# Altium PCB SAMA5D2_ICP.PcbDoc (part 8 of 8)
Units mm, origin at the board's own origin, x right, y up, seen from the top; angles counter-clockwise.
Board outline 150 x 100 mm, 6 copper layers (L1 - TOP, L2 - GND, L3 - SIG, L4 - SIG, L5 - VCC, L6 - BOT), stack 1.512 mm thick; 708 components, 597 nets, 2710 pads, 1437 vias.
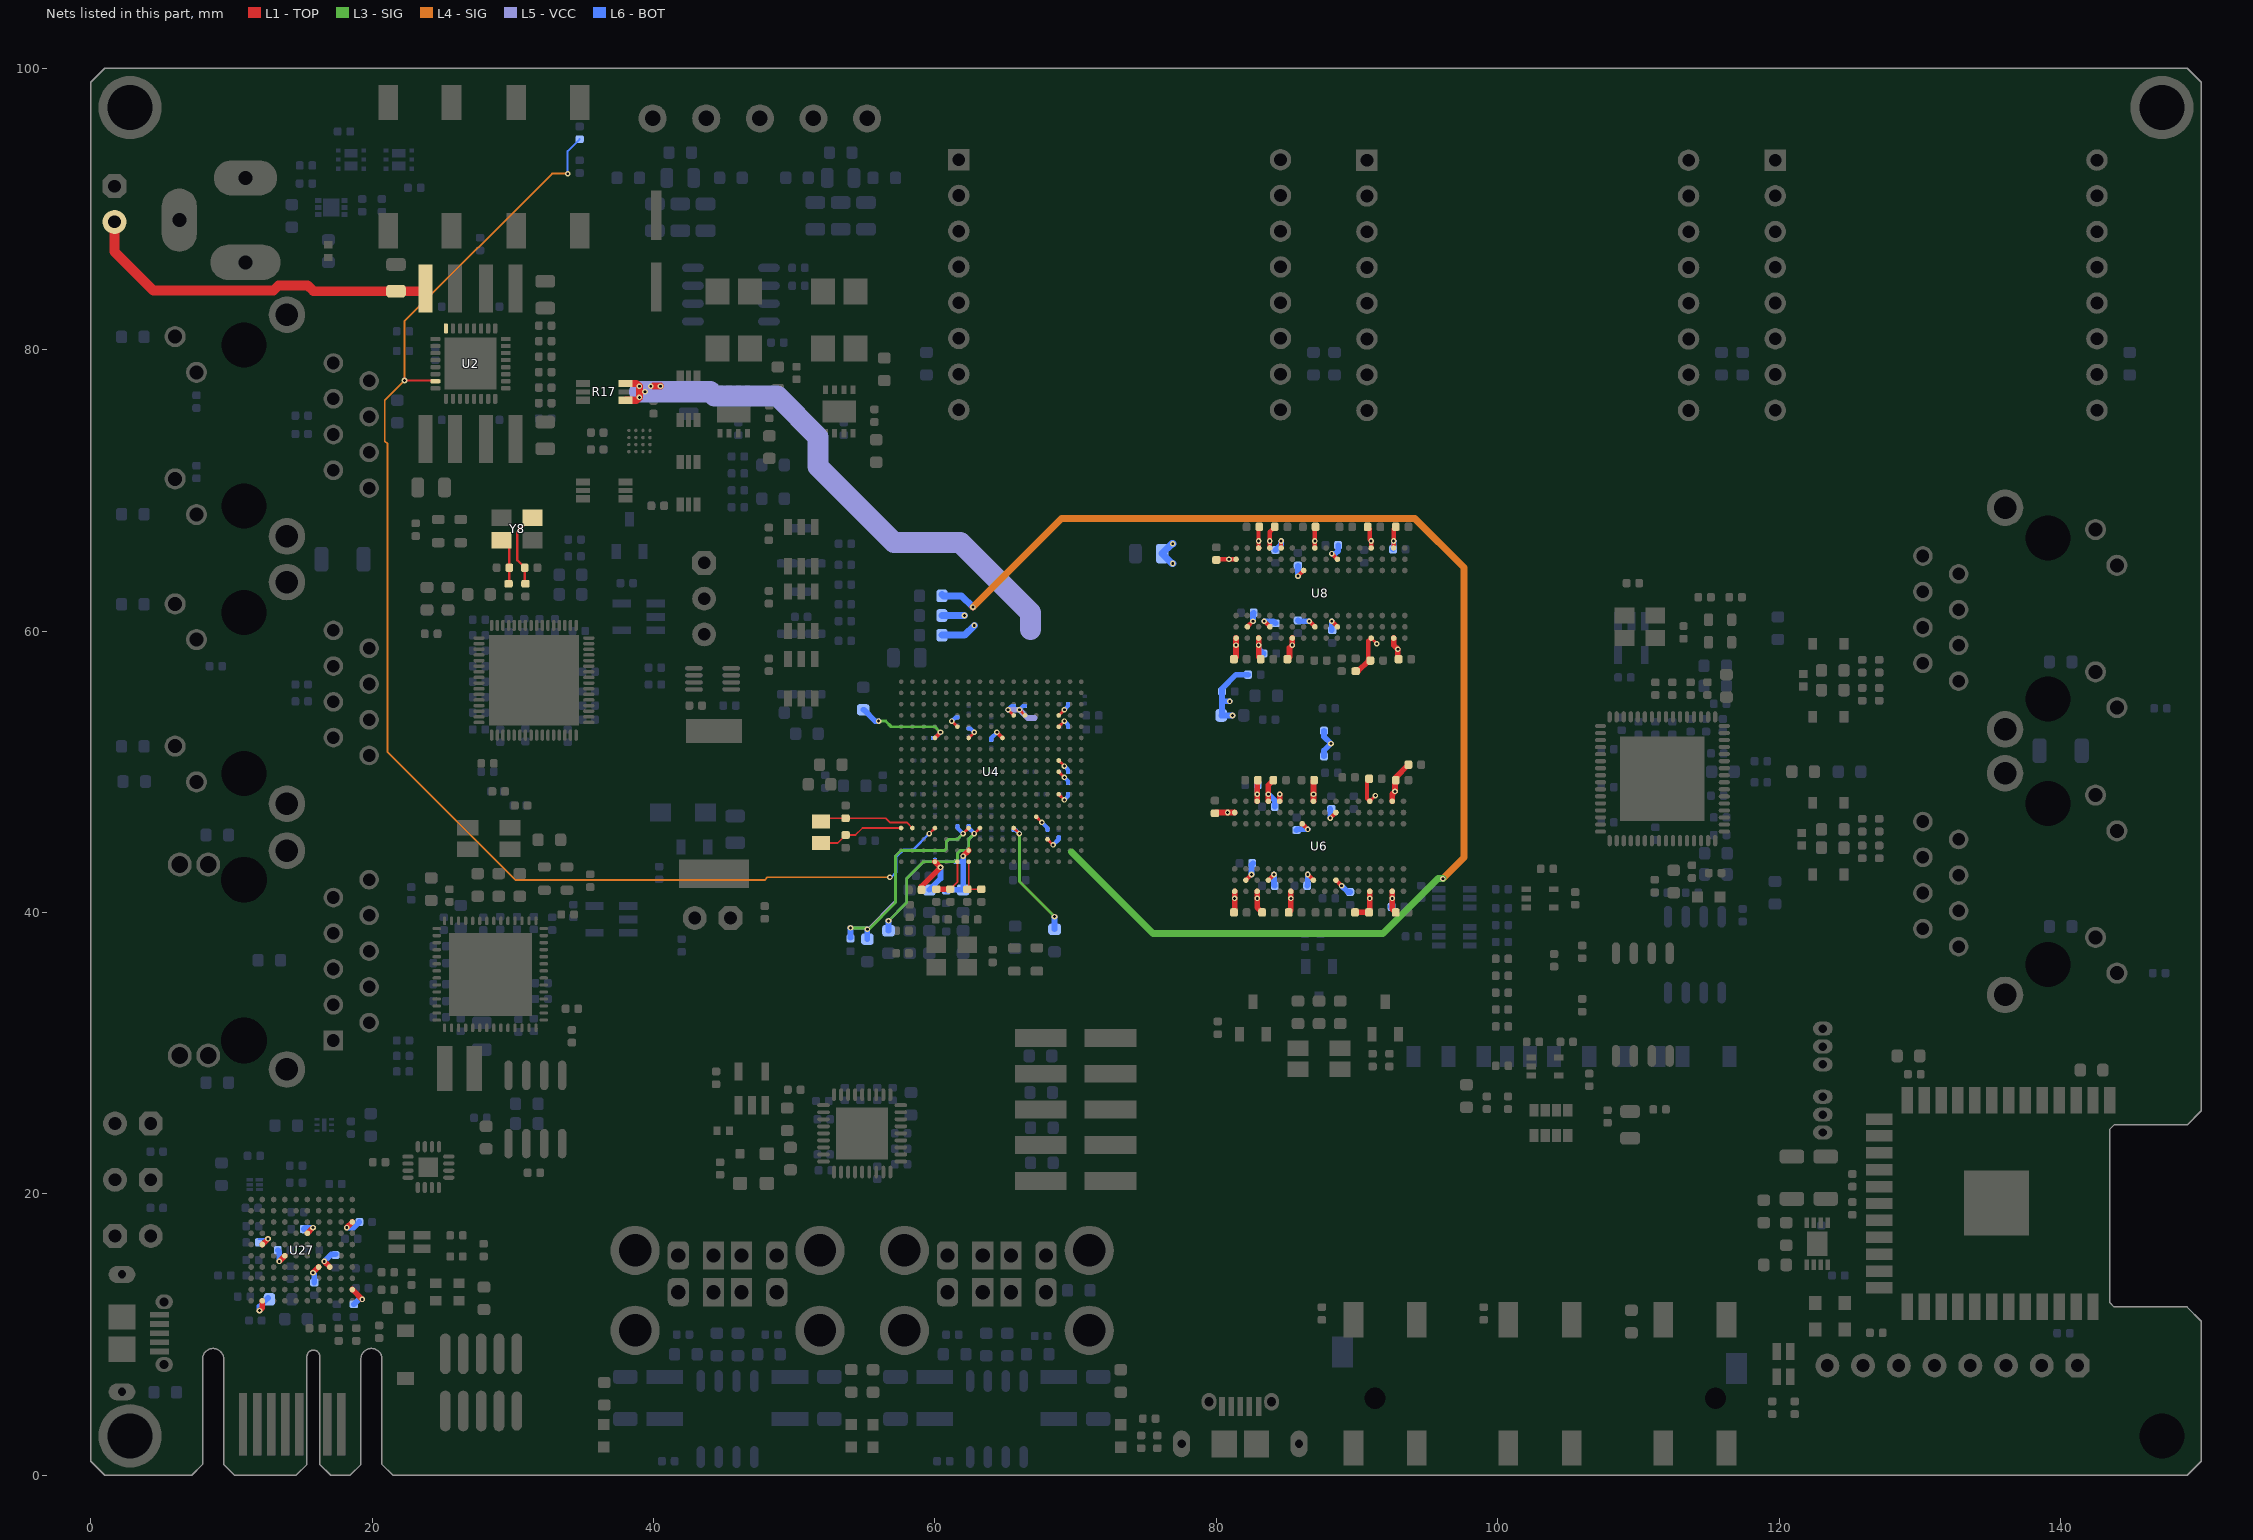
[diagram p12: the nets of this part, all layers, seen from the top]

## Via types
v1: diameter 0.4, hole 0.2, L1 - TOP to L6 - BOT, tented both sides, 1312 vias
v2: diameter 0.55, hole 0.3, L1 - TOP to L6 - BOT, 84 vias
v3: diameter 0.4, hole 0.2, L1 - TOP to L6 - BOT, tented top, 25 vias
v4: diameter 0.55, hole 0.3, L1 - TOP to L6 - BOT, tented bottom, 16 vias

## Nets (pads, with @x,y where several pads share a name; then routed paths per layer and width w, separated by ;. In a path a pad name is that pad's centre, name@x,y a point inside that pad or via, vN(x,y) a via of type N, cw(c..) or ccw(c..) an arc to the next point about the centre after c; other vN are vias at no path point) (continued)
VDDIODDR: C23.2 C25.2 C30.2 C33.2 C36.2 C40.2 C43.2 C45.2 C49.2 C54.2 C75.2 C76.2 C77.2 C79.2 C80.2 C81.2 C82.2 C83.2 C84.2 C86.2 C87.2 C88.2 C89.2 C90.2 C91.2 C93.2 C94.2 C95.2 C96.2 C97.2 C99.2 C100.2 C101.2 C102.2 C103.2 C104.2 C105.2 C106.2 C107.2 C108.2 C110.2 C111.2 C112.2 C113.2 C114.2 C115.2 C117.2 C118.2 C120.2 C121.2 R17.2 R25.2 R65.1 R86.1 R89.1 R94.1 R178.1 U4.D11 U4.D12 U4.D15 U4.E15 U4.H15 U4.J15 U4.L15 U6.A1 U6.A8 U6.B2 U6.C1 U6.C9 U6.D2 U6.D9 U6.E9 U6.F1 U6.G7 U6.H2 U6.H9 U6.K2 U6.K8 U6.N1 U6.N9 U6.R1 U6.R9 U8.A1 U8.A8 U8.B2 U8.C1 U8.C9 U8.D2 U8.D9 U8.E9 U8.F1 U8.G7 U8.H2 U8.H9 U8.K2 U8.K8 U8.N1 U8.N9 U8.R1 U8.R9 | length 120.7
  L1 - TOP w0.2: v1(65.2,54.4) U4.D11@65.6,54 ; v1(66,54.4) U4.D12@66.4,54 ; U4.L15@68.8,48.4 v1(69.2,48) ; U4.J15@68.8,50 v1(69.2,49.6) ; U4.H15@68.8,50.8 v1(69.2,50.4) ; U4.E15@68.8,53.2 v1(69.2,53.6) ; U4.D15@68.8,54 v1(69.2,54.4) ; U6.N9@90.9,47.9 v1(91.3,48.3) ; U8.N1@91,59.5 v1(91.4,59.1)
  L1 - TOP w0.25: C104.2@90.7,49.35 C104.2@90.85,49.5 ; C96.2@90.8,58.05 C96.2@90.95,57.9
  L1 - TOP w0.3: C82.2@80,65.05 80.05,65.1 v1(80.9,65.1) U8.A8@81.4,65.1 ; U6.B2@82.1,42.3 v1(82.5,42.7) ; U8.B2@82.2,60.3 v1(82.6,60.7) ; U8.C9@83,65.9 v1(83,66.4) 83,67.35 C76.2@83.05,67.4 ; v1(83.4,60.7) U8.D2@83.8,60.3 ; U6.D2@83.7,42.3 v1(84.1,42.7) ; U8.D9@83.8,65.9 v1(83.8,66.4) 83.8,67.05 C77.2@84.15,67.4 ; U8.E9@84.6,65.9 v1(84.6,66.4) ; v1(85.8,63.9) U8.G7@86.2,64.3 ; U6.G7@86.1,46.3 v1(86.5,45.9) ; v1(86.5,42.7) U6.H2@86.9,42.3 ; v1(86.6,60.7) U8.H2@87,60.3 ; U8.H9@87,66 v1(87,66.4) 87,67.35 C79.2@87.05,67.4 ; v1(88.1,46.7) U6.K8@88.4,47 ; v1(88.2,60.7) U8.K2@88.6,60.3 ; v1(88.2,65.5) U8.K8@88.55,65.15 ; U6.K2@88.5,42.3 v1(88.9,41.9) ; C104.2@90.7,49.35 90.7,48.1 U6.N9@90.9,47.9 ; C80.2@90.75,67.4 90.9,67.25 90.9,66.5 v1(91,66.4) U8.N9@91,65.9 ; C96.2@90.8,58.05 90.8,59.3 U8.N1@91,59.5 ; C104.2@90.832,49.518 C104.2@90.85,49.5 ; C96.2@90.932,57.882 C96.2@90.95,57.9 ; U8.R9@92.6,65.9 v1(92.6,66.4) 92.6,67.25 C81.2@92.75,67.4
  L1 - TOP w0.4: C106.2@79.9,47.05 79.95,47.1 v1(80.8,47.1) U6.A8@81.3,47.1 ; C115.2@81.25,40 81.3,40.05 v1(81.3,41) U6.A1@81.3,41.5 ; C93.2@81.25,58 81.4,58.15 v1(81.4,59) U8.A1@81.4,59.5 ; U6.C1@82.9,41.5 v1(82.9,41) 82.9,40.35 C117.2@83.25,40 ; U6.C9@82.9,47.9 v1(82.9,48.4) 82.9,49.35 C101.2@82.95,49.4 ; U8.C1@83,59.5 v1(83,59) 83,58.15 C94.2@83.15,58 ; U6.D9@83.7,47.9 v1(83.7,48.4) 83.7,49.05 C102.2@84.05,49.4 ; U6.E9@84.5,47.9 v1(84.5,48.4) ; C95.2@85.05,58 85.2,58.15 85.2,58.8 v1(85.4,59) U8.F1@85.4,59.5 ; C118.2@85.15,40 85.3,40.15 v1(85.3,41) U6.F1@85.3,41.5 ; U6.H9@86.9,47.9 v1(86.9,48.4) 86.9,49.35 C103.2@86.95,49.4 ; R86.1@89.85,40 C120.2@90.85,40 90.9,40.05 v1(90.9,41) U6.N1@90.9,41.5 ; R94.1@89.9,57.15 90.075,57.15 90.807,57.882 C96.2@90.932,57.882 ; U6.R1@92.5,41.5 v1(92.5,41) 92.5,40.25 C121.2@92.75,40 ; U6.R9@92.5,47.9 92.5,48.4 v1(92.7,48.6) 92.7,49.35 C105.2@92.75,49.4 92.75,49.6 R65.1@93.65,50.5 ; U8.R1@92.6,59.5 92.6,59 v1(92.9,58.7) 92.9,58.05 C97.2@92.95,58
  L1 - TOP w0.5: R17.2@38,76.4 38.8,76.4 v1(39,76.6) v1(39,77.4) 38.8,77.6 R17.2@38,77.6 ; 40,77.4 v1(40.5,77.4)
  L5 - VCC w0.4: v1(65.2,54.4) v1(66,54.4) 66.584,53.816 67.1,53.816
  L5 - VCC w1.5: 39,77 v1(39.4,77) 44.031,77 44.331,76.7 48.8,76.7 51.7,73.8 51.7,71.7 57.1,66.3 61.8,66.3 66.8,61.3 66.8,60.1
  L6 - BOT w0.3: v1(65.2,54.4) 65.462,54.662 C36.2@65.6,54.662 ; v1(66,54.4) 66.262,54.662 C40.2@66.4,54.662 ; v1(69.2,48) 69.462,48.262 C33.2@69.462,48.4 ; v1(69.2,49.6) 69.462,49.338 C43.2@69.462,49.2 ; v1(69.2,50.4) 69.462,50.138 C45.2@69.463,50 ; v1(69.2,53.6) 69.462,53.338 C54.2@69.462,53.2 ; v1(69.2,54.4) 69.462,54.662 C49.2@69.463,54.8
  L6 - BOT w0.4: R25.2@80.35,54 R25.2@80.4,54 ; 80.4,55 v1(80.95,55) ; v1(81.15,54) R25.2@80.4,54 ; C23.2@82.25,56.9 81.4,56.9 80.4,55.9 R25.2@80.4,54 ; v1(82.5,42.7) 82.5,43.4 C111.2@82.6,43.5 ; v1(82.6,60.7) 82.6,61.25 C88.2@82.65,61.3 ; v1(82.9,48.4) 82.9,48.95 C99.2@82.95,49 ; v1(83,59) 83,58.75 C87.2@83.35,58.4 ; v1(83.4,60.7) 84.05,60.7 C89.2@84.2,60.55 ; v1(83.7,48.4) 84.15,47.95 C107.2@84.15,47.5 ; v1(84.1,42.7) 84.1,41.95 C112.2@84.15,41.9 ; C83.2@84.2,65.75 84.6,66.15 v1(84.6,66.4) ; C108.2@85.7,45.85 85.75,45.9 v1(86.5,45.9) ; C90.2@85.8,60.75 85.85,60.7 v1(86.6,60.7) ; v1(85.8,63.9) C84.2@85.8,64.65 ; C113.2@86.45,41.9 86.5,41.95 v1(86.5,42.7) ; R178.1@87.65,51.1 87.65,51.511 88.139,52 87.65,52.489 R89.1@87.65,52.9 ; v1@88.1,46.763 C110.2@88.1,47.35 ; C91.2@88.2,60.05 v1(88.2,60.7) ; v1@88.237,65.5 88.461,65.5 88.65,65.689 C86.2@88.65,66.1 ; v1(88.9,41.9) 89.35,41.45 C114.2@89.5,41.45 ; C100.2@92.4,40.4 92.5,40.5 v1(92.5,41) ; C75.2@92.55,65.8 92.6,65.85 v1(92.6,66.4)
  L6 - BOT w0.5: v1(76.9,64.8) 76.85,64.8 C30.2@76.15,65.5 76.85,66.2 v1(76.9,66.2)
  other v1: 88.15,52 39.8,77.4
VDDIOP0: C37.2 C41.2 FB3.2 U4.E6 U4.F7 | length 3.7
  L1 - TOP w0.2: v1(61.2,53.6) U4.E6@61.6,53.2 ; U4.F7@62.4,52.4 v1(62.8,52.8)
  L6 - BOT w0.3: v1(61.2,53.6) 61.462,53.862 C41.2@61.6,53.862 ; C37.2@62.4,53.062 62.538,53.062 v1(62.8,52.8)
  L6 - BOT w0.5: FB3.2@60.5,61.1 v1(62.1,61.1)
VDDIOP1: C46.2 C50.2 FB4.2 U4.N13 U4.R14 | length 97.2
  L1 - TOP w0.2: U4.N13@67.2,46.8 v1(67.6,46.4) ; U4.R14@68,45.2 v1(68.4,44.8)
  L3 - SIG w0.5: 69.7,44.3 75.5,38.5 91.85,38.5 95.75,42.4 v1(96.1,42.4)
  L4 - SIG w0.5: v1(62.7,61.7) 69,68 94.1,68 97.6,64.5 97.6,43.9 v1(96.1,42.4)
  L6 - BOT w0.3: v1(67.6,46.4) 68,46 C50.2@68,45.862 ; v1(68.4,44.8) 68.8,45.2 C46.2@68.8,45.338
  L6 - BOT w0.5: FB4.2@60.5,62.6 60.6,62.5 61.9,62.5 v1(62.7,61.7)
VDDIOP2: C38.2 FB5.2 U4.F10 | length 3.9
  L1 - TOP w0.3: v1(64.4,52.8) U4.F10@64.8,52.4
  L6 - BOT w0.3: C38.2@64,52.262 64,52.4 v1(64.4,52.8)
  L6 - BOT w0.5: FB5.2@60.5,59.7 62.1,59.7 v1(62.8,60.4)
VDDISC: C73.2 FB6.2 U4.F4 | length 7.4
  L1 - TOP w0.3: U4.F4@60,52.4 v1(60.4,52.8)
  L3 - SIG w0.2: v1(56,53.6) 56.5,53.6 56.9,53.2 60,53.2 v1(60.4,52.8)
  L6 - BOT w0.3: C73.2@59.862,52.4 60,52.4 v1(60.4,52.8)
  L6 - BOT w0.4: FB6.2@54.9,54.4 54.95,54.4 55.75,53.6 v1(56,53.6)
VDDOSC: C71.2 C72.2 L6.2 U4.T7 | length 4.8
  L1 - TOP w0.4: v1(62,44) U4.T7@62.4,44.4
  L6 - BOT w0.3: C72.2@61.462,43.6 61.9,43.6 62,43.7
  L6 - BOT w0.4: C71.2@60.8,41.55 60.85,41.6 L6.2@62,41.6 62,43.7 v1(62,44)
VDDout: C258.2 C260.2 C262.2 C264.2 C266.2 C268.2 C270.2 C272.2 U27.A9 U27.B1 U27.D3 U27.D4 U27.E7 U27.F9 U27.G5 U27.H1 | length 12.1
  L1 - TOP w0.4: v1(12,11.7) 12.2,11.9 U27.A9@12.2,12.4 ; U27.F9@12.2,16.4 v1(12.6,16.8) ; v1(13.4,15.2) U27.E7@13.8,15.6 ; U27.G5@15.4,17.2 v1(15.8,17.6) ; v1(15.8,14.4) U27.D4@16.2,14.8 ; v1(16.6,15.2) U27.D3@17,14.8 ; v1(18.2,17.6) U27.H1@18.6,18 ; U27.B1@18.6,13.2 v1(19.3,12.5)
  L6 - BOT w0.15: C270.2@11.95,16.8 v1(12.6,16.8)
  L6 - BOT w0.4: v1(12,11.7) 12,12 C258.2@12.6,12.6 ; C268.2@13.3,16 13.4,15.9 v1(13.4,15.2) ; C264.2@15.15,17.5 15.25,17.6 v1(15.8,17.6) ; v1(15.8,14.4) 15.9,14.3 C260.2@15.9,13.7 ; v1(16.6,15.2) 17.1,15.7 C266.2@17.4,15.7 ; v1(18.2,17.6) 18.7,17.6 C272.2@19.1,18 ; C262.2@18.7,12.15 19.05,12.5 v1(19.3,12.5)
VDDPLLA: C69.2 C70.2 L5.2 U4.U4 | length 5.4
  L1 - TOP w0.4: C69.2@59.05,41.6 59.05,41.85 v1(60.4,43.2) U4.U4@60,43.6
  L6 - BOT w0.3: C70.2@60,43.738 60,43.6 v1(60.4,43.2)
  L6 - BOT w0.4: L5.2@59.6,41.6 60.4,42.4 v1(60.4,43.2)
VDDSDHC: C66.2 FB9.2 U4.P11 | length 15.8
  L1 - TOP w0.2: U4.P11@65.6,46 v1(66,45.6)
  L3 - SIG w0.2: v1(66,45.6) 66,42.2 v1(68.5,39.7)
  L4 - SIG w0.2: v1(66,45.6) 66,42.2 v1(68.5,39.7)
  L6 - BOT w0.3: C66.2@65.6,45.862 65.738,45.863 v1(66,45.6)
  L6 - BOT w0.4: FB9.2@68.5,38.8 v1(68.5,39.7)
VDDUTMIC: C62.2 C65.2 FB1.2 U4.P7 | length 28.8
  L1 - TOP w0.2: v1(62,45.6) U4.P7@62.4,46
  L3 - SIG w0.2: v1(54,38.9) 55.1,38.9 v1(55.2,38.8) 55.3,38.8 57.2,40.7 57.2,44 57.6,44.4 60.7,44.4 60.8,44.5 60.8,45 61,45.2 61.6,45.2 v1(62,45.6)
  L5 - VCC w0.2: v1(54,38.9) 55.1,38.9 v1(55.2,38.8) 57.2,40.8 57.2,44 57.6,44.4 60.7,44.4 60.8,44.5 60.8,45 61,45.2 61.6,45.2 v1(62,45.6)
  L6 - BOT w0.3: C65.2@61.6,46.138 61.6,46 v1(62,45.6)
  L6 - BOT w0.4: C62.2@54,38.2 v1(54,38.9) ; FB1.2@55.2,38.1 v1(55.2,38.8)
VDDUTMII: C64.2 FB7.2 U4.P8 | length 22.5
  L1 - TOP w0.2: v1(62.8,45.6) U4.P8@63.2,46
  L3 - SIG w0.2: v1(56.7,39.4) 58,40.7 58,42.4 59.2,43.6 61.4,43.6 61.6,43.8 61.6,44.2 61.8,44.4 62.2,44.4 62.4,44.6 62.4,45.2 v1(62.8,45.6)
  L5 - VCC w0.2: v1(56.7,39.4) 58,40.7 58,42.4 59.2,43.6 61.4,43.6 61.6,43.8 61.6,44.2 61.8,44.4 62.2,44.4 62.4,44.6 62.4,45.2 v1(62.8,45.6)
  L6 - BOT w0.3: C64.2@62.4,46.138 62.4,46 v1(62.8,45.6)
  L6 - BOT w0.4: FB7.2@56.7,38.7 v1(56.7,39.4)
Vout4: C18.1 J3.2 L4.2 U2.32 | length 25.8
  L1 - TOP w0.7: J3.2@1.7,89.073 1.7,86.95 4.45,84.2 13,84.2 13.35,84.55 15.425,84.55 15.825,84.15 C18.1@21.7,84.15 23.6,84.15 L4.2@23.8,84.35
WAKE_UP: R256.1 U2.7 U4.P4 | length 97.1
  L1 - TOP w0.165: v1(22.3,77.8) 24.45,77.8 U2.7@24.5,77.75 ; v1(59.6,45.6) U4.P4@60,46
  L4 - SIG w0.14: v1(33.9,92.5) 32.8,92.5 22.3,82 v1(22.3,77.8) 20.9,76.4 20.9,73.5 21.1,73.3 21.1,51.4 30.2,42.3 47.9,42.3 48.1,42.5 v1(56.8,42.5)
  L6 - BOT w0.14: v1(33.9,92.5) 33.9,94.1 R256.1@34.75,94.95
  L6 - BOT w0.165: v1(56.8,42.5) 56.9,42.5 57.275,42.875 57.275,43.95 57.8,44.475 58.475,44.475 v1(59.6,45.6)
Xi1: C183.2 R147.1 Y8.1 | length 3.3
  L1 - TOP w0.165: Y8.1@29.2,66.45 29.75,65.9 C183.2@29.75,64.5 29.75,63.4 R147.1@29.7,63.35
Xin: R69.2 R70.2 U4.U7 | length 3
  L1 - TOP w0.125: U4.U7@62.4,43.6 62.4,41.75 R70.2@62.3,41.65 R69.2@63.3,41.65
Xin_32: C51.2 U4.P1 Y1.2 | length 6.1
  L1 - TOP w0.125: Y1.2@51.9,44.938 53.088,44.938 C51.2@53.65,45.5 54.35,45.5 54.85,46 U4.P1@57.6,46
Xo1: C189.2 R146.1 Y8.3 | length 5.4
  L1 - TOP w0.165: R146.1@30.9,63.35 30.85,63.4 C189.2@30.85,64.5 30.325,65.025 30.325,67.075 31.3,68.05 Y8.3@31.4,68.05
Xout: R5.2 R71.2 U4.U6 | length 3.2
  L1 - TOP w0.125: R71.2@61.1,41.65 61.6,42.15 U4.U6@61.6,43.6
  L1 - TOP w0.4: R5.2@60.1,41.65 R71.2@61.1,41.65
Xout_32: C299.2 U4.P2 Y1.1 | length 6.9
  L1 - TOP w0.125: Y1.1@51.9,46.462 52.138,46.7 C299.2@53.65,46.7 56.5,46.7 56.8,46.4 58,46.4 U4.P2@58.4,46
pads on no net: J1.3 J5.1.5mm J9.4 J10.3.25mm J10.10 J11.3.20mm J11.7 J12.3.20mm J12.7 J13.3.20mm J13.7 J13.11 J13.12 J14.3.20mm J14.7 J14.11 J14.12 J15.1 J15.7 J15.9 J15.11 J15.13 J15.15 J16.4 U1.3 U4.J5 U4.K2 U4.N4 U4.T1 U4.U1 U4.U3 U6.J1 U6.J9 U6.L1 U6.L9 U6.M7 U6.T7 U8.J1 U8.J9 U8.L1 U8.L9 U8.M7 U8.T7 U15.5 U15.32 U15.34 U19.15 U19.36 U19.37 U19.47 U24.3 U24.18 U24.34 U26.5 U27.A3 U27.A4 U27.A5 U27.A6 U27.A10 U27.B4 U27.B5 U27.B6 U27.B10 U27.C4 U27.C5 U27.C6 U27.D5 U27.D7 U27.E4 U27.E8 U27.E9 U27.E10 U27.F1 U27.F2 U27.F7 U27.F8 U27.F10 U27.G1 U27.G2 U27.G3 U27.G4 U27.G7 U27.G9 U27.H2 U27.H3 U27.H10 U27.J1 U27.J2 U27.J4 U27.J5 U27.J6 U27.J7 U27.K5 U27.K6 U32.3 U32.4 U32.5 U32.6 U32.14 U33.7 U34.1 U34.2 U34.3 U34.7 Y12.3

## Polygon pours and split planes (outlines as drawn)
NetFB3_1 on L6 - BOT "full" (solid, remove dead copper, pour order 452): 55.6,59.4 55.6,60.5 57.8,62.7 58.3,62.7 58.3,59.4
DDR_REF on L6 - BOT "DDR_VREF" (solid, remove dead copper, pour order 457): 76.25,46.6 76.25,49.036 79.807,52.593 79.852,52.7 79.852,59.2 87.8,59.2 87.8,40.8 82.05,40.8
NetC6_2 on L6 - BOT "full" (solid, remove dead copper, pour order 453): 17.7,90.4 17.8,90.4 21.1,90.4 21.1,93.7 17.7,93.7
VDD_MAIN_5V on L6 - BOT "full" (solid, remove dead copper, pour order 454): 19.1,94 19.1,96.1 24.5,96.1 24.5,90 24.25,90 23.2,90 23.2,91.25 23.2,94
GND on L6 - BOT "full" (solid, remove dead copper, pour order 456): 33.9,30.855 33.9,40.805 33.85,40.855 23.4,40.855 23.4,30.855
GND on L6 - BOT "BOARD_GND_PLANE" (solid, remove dead copper, pour order 459): 0,0 150,0 150,100 0,100
NetC1_2 on L6 - BOT "PAD-U1" (solid, remove dead copper, pour order 458): 0,95 17.7,95 17.7,88.148 18.3,87.548 23.1,87.548 23.1,81.8 0,81.8
3V3 on L3 - SIG "full" (solid, remove dead copper, pour order 440): 0,100 150,100 150,0 0,0
DDR_REF on L3 - SIG "full" (solid, remove dead copper, pour order 434): 69.6,53.6 69.6,50 73.043,50 76.743,46.3 77.3,46.3 79.3,48.3 79.3,48.4 73.7,54 70,54
VDDIOP1 on L3 - SIG "full" (solid, remove dead copper, pour order 433): 67.1,46.9 67.1,45.3 69.4,43 71,43 70.994,44.606 68.7,46.9
DDR_REF on L3 - SIG "full" (solid, remove dead copper, pour order 435): 90.1,65 90.1,53.9 81.25,53.9 79.3,55.85 79.3,65
1V25 on L3 - SIG "full" (solid, remove dead copper, pour order 436): 34.987,65.1 36.043,66.157 37,65.2 37,51.3 25,51.3 25,65.1
VDDout on L3 - SIG "full" (solid, remove dead copper, pour order 437): 0,26.5 0,0 20,0 20,26.5
VDD33TXRX2 on L3 - SIG "full" (solid, remove dead copper, pour order 438): 116.5,69.1 150,69.1 150,52.7 116.5,52.7
VDD33TXRX1 on L3 - SIG "full" (solid, remove dead copper, pour order 439): 116.5,50.2 150,50.2 150,33.8 116.5,33.8
GND on L4 - SIG "full" (solid, remove dead copper, pour order 443): 132.9,16.9 137.9,16.9 137.9,21.8 132.9,21.8
GND on L4 - SIG "full" (solid, remove dead copper, pour order 446): 0,100 150,100 150,0 0,0
DDR_REF on L4 - SIG "full" (solid, remove dead copper, pour order 444): 88.5,47.1 92,47.1 92,40.6 86.5,40.6 86.5,43.2 88.5,45.2
VDDIOP2 on L4 - SIG "full" (solid, remove dead copper, pour order 441): 62.5,60.7 62.5,58.3 62.9,57.9 62.9,54 63.1,53.8 63.1,52.4 64.6,52.4 64.6,53.4 63.7,54.3 63.7,60.7
VDDIOP0 on L4 - SIG "full" (solid, remove dead copper, pour order 442): 61,61.4 62.1,61.4 62.4,61.1 62.4,58.2 62.8,57.8 62.8,53.6 62.9,53.5 62.9,52.4 61,52.4
"Earth USB" on L4 - SIG "full" (solid, remove dead copper, pour order 445): 0,19 0,0 87.5,0 87.5,19
"GND ETH3" on L1 - TOP "full" (solid, remove dead copper, pour order 428): 0,26.7 21.855,26.7 21.8,26.755 21.8,46.005 0,46.005
"GND ETH" on L1 - TOP "full" (solid, remove dead copper, pour order 429): 0,83.4 0.037,83.363 22.2,83.363 22.2,46.25 0,46.25
"Earth USB" on L1 - TOP "full" (solid, remove dead copper, pour order 430): 36,19 36,0 87.5,0 87.5,19
GND on L1 - TOP "full" (solid, remove dead copper, pour order 426): 42.6,93.1 42.6,87.65 38.1,87.65 38.1,93.1
VDD_MAIN_5V on L1 - TOP "full" (solid, remove dead copper, pour order 427): 42.119,86.306 42.119,81.6 38.119,81.6 38.119,86.306
3V3 on L5 - VCC "3V3" (solid, remove dead copper, pour order 451): 0.037,100 150,100 150,0 -0.279,0
VDDCORE on L5 - VCC "VDDCORE" (solid, remove dead copper, pour order 447): 57.3,63.4 57.3,56.8 58.4,55.7 58.4,46 67.2,46 66.9,46.3 66.9,59.1 63.6,59.1 59.3,63.4
VDDIODDR on L5 - VCC "VDDIODDR" (solid, remove dead copper, pour order 450): 62.6,60.7 62.6,55.1 64.6,53.1 64.6,49 75.8,37.8 80.3,37.8 82,39.5 94.1,39.5 96.5,41.9 96.5,65.5 88.8,73.2 51.6,73.2 51.6,71.7
VDD_3V3_JLINK on L5 - VCC "VDD_3V3_JLINK" (solid, remove dead copper, pour order 448): 0,27 0,0 24,0 24,27
VDD_MAIN_5V on L5 - VCC "VDD_MAIN_5V" (solid, remove dead copper, pour order 449): 0.082,83.4 22.8,83.4 22.8,75.325 40,75.325 40,100.112 0,100 0.082,99.918
GND on L2 - GND "GND" (solid, remove dead copper, pour order 432): 1,0 7.18,0 7.955,0.775 7.955,8.265 cw(c8.705,8.265) 9.455,8.265 9.455,0.775 10.23,0 14.598,0 15.373,0.775 15.373,8.443 cw(c15.83,8.443) 16.287,8.443 16.287,0.775 17.062,0 18.43,0 19.205,0.775 19.205,8.265 cw(c19.955,8.265) 20.705,8.265 20.705,0.775 21.48,0 149,0 150,1 150,9.8 148.985,10.815 143.8,10.815 143.5,11.115 143.5,24.6 143.8,24.9 149,24.9 150,25.9 150,32 150,68 150,99 149,100 1,100 0,99 0,1

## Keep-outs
Keep-Out Layer:
  region: 150,33 143.6,33 143.6,27.9 144.2,27.9 144.2,25.4 143.5,25.4 143.5,0 150,0
  text ".Layer_Name" at 300.5,-108.75 h1.5

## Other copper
L1 - TOP:
  rectangle net VDDIODDR: 91.4,59.1 91.4,59.3
  rectangle net USBD1_n: 44.907,14.63 45.136,16.637
  rectangle net USBD1_p: 45.364,14.63 45.593,16.637
  rectangle net USBD3_p: 64.516,14.63 64.745,16.637
  rectangle net USBD3_n: 64.059,14.63 64.287,16.637
  pour cut-out: 142.9,25.55 128.294,25.55 128.294,13.116 142.9,13.116
  region net 3V3: 25.2,76.15 25.2,76.85 24.125,76.85 23.3,76.025 23.3,74.875 24.3,74.875 24.3,75.9 24.55,76.15
  region net NetFB7_1: 42.9,73.2 44.085,73.2 44.084,71.5 42.9,71.5
  region net VDDCORE: 42.9,75.1 44.085,75.1 44.185,75 44.185,73.885 44.1,73.8 42.9,73.8
  region net VDDIODDR: 38.9,76.3 39.1,76.3 40.2,77.4 40.2,77.7 38.9,77.7
  region net GND: 92,49.5 92,47.9 91.8,47.7 91.7,47.7 91.7,48.5 91.5,48.7 91.3,48.7 91.3,49.1 91.5,49.3 91.5,49.5
  region net VDDIODDR: 91.3,48.1 91.1,47.9 90.7,47.9 90.7,48.9 91.1,48.5 91.3,48.5
  region net VDDIODDR: 91.4,59.3 91.2,59.5 90.8,59.5 90.8,58.5 91.2,58.9 91.4,58.9
  region net GND: 91.8,58.9 91.6,58.7 91.4,58.7 91.4,58.3 91.8,57.9
  region net NetL2_1: 27.9,76.75 27.9,75.875 28.6,75.175 28.6,71.95 27.6,71.95 27.6,76.75
  region net 1V35: 28.8,76.15 28.8,76.85 29.875,76.85 30.7,76.025 30.7,74.875 29.7,74.875 29.7,75.9 29.45,76.15
  region net NetL1_1: 26.1,76.75 26.1,75.875 25.4,75.175 25.4,71.95 26.4,71.95 26.4,76.75
  region net NetL4_1: 26.1,81.25 26.1,82.125 25.4,82.825 25.4,86.05 26.4,86.05 26.4,81.25
  region net Vout4: 25.2,81.85 25.2,81.15 24.125,81.15 23.3,81.975 23.3,83.125 24.3,83.125 24.3,82.1 24.55,81.85
  region net 1V25: 28.8,81.85 28.8,81.15 29.875,81.15 30.7,81.975 30.7,83.125 29.7,83.125 29.7,82.1 29.45,81.85
  region net NetL3_1: 27.9,81.25 27.9,82.125 28.6,82.825 28.6,86.05 27.6,86.05 27.6,81.25
  text "'.Layer_Name'" at 0,101 h1
  text "1" at 149,80.9 h1 r90
  text ".ProjectRevisionART" at 335.678,-108.572 h1.5
  text ".Layer_Name" at 300.5,-108.75 h1.5
L2 - GND:
  text "'.Layer_Name'" at 0,101 h1
  text "2" at 149,83.087 h1 r90
L3 - SIG:
  text "'.Layer_Name'" at 0,101 h1
  text "3" at 149,85.273 h1 r90
L4 - SIG:
  text "'.Layer_Name'" at 0,101 h1
  text "4" at 149,88.127 h1 r90
L5 - VCC:
  region net NetFB7_1: 41.8,73.2 44,73.2 44,70.7 41.8,70.7
  text "'.Layer_Name'" at 0,101 h1
  text "5" at 149,90.313 h1 r90
L6 - BOT:
  rectangle net VBUS_JLINK: 6.287,11.2 7.5,12.9
  pour cut-out: 16.568,8.443 16.568,10.1 14.6,10.1 14.6,8.443
  pour cut-out: 17.3,6.1 19.205,6.1 19.2,-0.1 17.3,-0.1
  region net VBUS_JLINK: 17.775,93 16.3,93 16,93.3 15.5,93.3 15.5,91.6 16,91.6 16.2,91.8 16.825,92.2
  region net 3V3: 23.2,72.45
  region: 76.3,71.7
  region net VDDIODDR: 30.8,72.45
  region: 28.2,72.45
  region: 35.8,85.55
  region: 28.2,85.55
  region net 2V5_LAN: 23.4,33.055 24.6,33.055 24.6,41.255 23.4,41.255
  text "'.Layer_Name'" at 0,101 h1
  text "6" at 149,92.5 h1 r90
  text ".ProjectRevisionART" at 335.678,-108.572 h1.5
  text ".ProjectRevisionART" at 335.678,-108.572 h1.5
  text ".ProjectRevisionART" at 335.678,-108.572 h1.5
  text ".Layer_Name" at 300.5,-108.75 h1.5
Multi-Layer:
  pour cut-out: 150,93.6 147,93.6 147,79.5 150,79.5
  text "Exported with Altium Designer .Application_BuildNumber on .Print_Date at .Print_Time" at 15.5,101 h1

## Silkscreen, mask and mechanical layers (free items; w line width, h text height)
Top Overlay:
  drawing of 3283 lines, arcs and shapes, not listed
  text "'.Layer_Name'" at 0,101 h1
  text "Exported with Altium Designer .Application_BuildNumber on .Print_Date at .Print_Time" at 15.5,101 h1
  text "CAN" at 37.1,95.8 h1 r90
  text "GND" at 0.4,93.6 h1
  text "RESET" at 28.725,90.7 h1 r90
  text "START" at 19.6,90.4 h1 r90
  text "5V DC" at 17.1,89.3 h1 r90
  text "GND" at 48.2,88.4 h1 r90
  text "Vout4" at 0.3,86.101 h1
  text "1-CANH" at 45.2,85.5 h1 r90
  text "1-CANL" at 46.8,85.5 h1 r90
  text "2-CANL" at 55.8,85.22 h1 r90
  text "2-CANH" at 52,85.1 h1 r90
  text "port 1" at 15.05,83.8 h1
  text "Ethernet" at 5,83.7 h1
  text "port-B" at 143.9,70 h1
  text "ETHERCAT" at 106.25,67.65 h1.5
  text "Ethernet" at 5,64.6 h1
  text "port 2" at 15.5,64.6 h1
  text "GND" at 38.8,64.4 h1
  text "GPIO_2" at 36.4,61.7 h1
  text "e" at 95.8,61.4 h10
  text "M" at 58.2,59.7 h10
  text "GPIO_1" at 36.4,59.1 h1
  text "C" at 72.05,52.75 h10
  text "" at 97.2,52.7 h10
  text "port-A" at 143.8,51.1 h1
  text "HSIC" at 22.55,49.8 h1
  text "status" at 22.55,48.6 h1
  text "Gigabit" at 6.3,45.7 h1
  text "Ethernet" at 14.917,45.642 h1
  text "" at 96.7,43.7 h10
  text "VDDBU" at 41.9,36.6 h1
  text "EESCL" at 116.675,31.4 h1
  text "WIFI/BLE" at 131.7,30.675 h1.5
  text "GND" at 62.1,30.6 h1
  text "PD31" at 75.2,30.6 h1
  text "EESDA" at 116.675,29.998 h1
  text "GND" at 118.7,28.6 h1
  text "PC25" at 61.1,28 h1
  text "PC9" at 75.2,28 h1
  text "GND" at 118.7,26.6 h1
  text "User" at 85,26.4 h1
  text "DISABLE J-LINK OB" at 9.2,25.9 h1
  text "PC30" at 61.1,25.5 h1
  text "PIOBU6" at 75.2,25.5 h1
  text "UART_RXD" at 113.7,25.2 h1
  text "USB" at 40.7,24.7 h1
  text "LED" at 85,24.7 h1
  text "DISABLE J-LINK CDC" at 9.2,24.4 h1
  text "UART_TXD" at 113.7,23.798 h1
  text "suspend" at 36.7,23.328 h1
  text "PIOBU5" at 59.3,23 h1
  text "PIOBU4" at 75.2,23 h1
  text "ERASE" at 9.2,22.9 h1
  text "PIOBU2" at 75.2,21 h1
  text "PIOBU3" at 59.3,20.3 h1
  text "rev.C" at 106,18.5 h1
  text "USB" at 52.8,18.4 h1.5
  text "SAMA5D2-ICP" at 81.3,17.7 h2
  text "J7" at 74.2,17.1 h1
  text "INDUSTRIAL CONNECTIVITY PLATFORM" at 81.2,15.4 h1
  text "USB1" at 74.7,15 h1
  text "J8" at 80.125,13.1 h1
  text "USER_PB1" at 88.3,13.1 h1
  text "DIS_BOOT" at 99.2,13.1 h1
  text "USER_PB2" at 110.2,13 h1
  text "USB2" at 74.7,12.8 h1
  text "USB3" at 80.7,11 h1
  text "www.segger.com" at 9.3,10.1 h1 r90
  text "J-Link Technology" at 7.9,9.3 h1 r90
  text "USB4" at 80.7,8.8 h1
  text "JLINK" at 7.1,2.4 h1 r90
  text "GND" at 124,2 h1 r90
  text "3V3" at 141.8,2 h1 r90
  text "JTAG" at 25.9,0.8 h1
  text "GPIO17" at 126.4,0.6 h1 r90
  text "GPIO18" at 129,0.6 h1 r90
  text "GPIO19" at 131.5,0.6 h1 r90
  text "GPIO20" at 134.1,0.6 h1 r90
  text "GPIO0" at 136.6,0.6 h1 r90
  text "GPIO21" at 139.2,0.6 h1 r90
  text "WILC activity" at 118.5,0.5 h1 r90
  text ".ProjectRevisionART" at 335.678,-108.572 h1.5
  text ".Layer_Name" at 300.5,-108.75 h1.5
Bottom Overlay:
  drawing of 3285 lines, arcs and shapes, not listed
  text "'.Layer_Name'" at 0,101 h1
  text "Exported with Altium Designer .Application_BuildNumber on .Print_Date at .Print_Time" at 15.5,101 h1
  text "5V DC" at 13.3,95.8 h1
  text "Ethernet" at 2.4,78.4 h1 r90
  text "port A" at 4.2,77.6 h1 r90
  text "Ethernet" at 2.4,60.1 h1 r90
  text "port B" at 4.1,59.1 h1 r90
  text "port-B" at 146.1,58.1 h1 r270
  text "EtherCAT" at 148,57.1 h1 r270
  text "Ethernet" at 4.4,45.1 h1 r90
  text "Gigabit" at 2.5,44 h1 r90
  text "port-A" at 146.2,39.1 h1 r270
  text "EtherCAT" at 148,38.1 h1 r270
  text "SD/MMC" at 118.3,14.5 h1 r270
  text ".ProjectRevisionART" at 335.678,-108.572 h1.5
  text ".Layer_Name" at 300.5,-108.75 h1.5
Top Paste:
  text "'.Layer_Name'" at 0,101 h1
  text "Exported with Altium Designer .Application_BuildNumber on .Print_Date at .Print_Time" at 15.5,101 h1
  text ".ProjectRevisionART" at 335.678,-108.572 h1.5
  text ".Layer_Name" at 300.5,-108.75 h1.5
Bottom Paste:
  text "'.Layer_Name'" at 0,101 h1
  text "Exported with Altium Designer .Application_BuildNumber on .Print_Date at .Print_Time" at 15.5,101 h1
  text ".ProjectRevisionART" at 335.678,-108.572 h1.5
  text ".Layer_Name" at 300.5,-108.75 h1.5
Top Solder:
  text "'.Layer_Name'" at 0,101 h1
  text "Exported with Altium Designer .Application_BuildNumber on .Print_Date at .Print_Time" at 15.5,101 h1
  text ".ProjectRevisionART" at 335.678,-108.572 h1.5
  text ".Layer_Name" at 300.5,-108.75 h1.5
Bottom Solder:
  text "'.Layer_Name'" at 0,101 h1
  text "Exported with Altium Designer .Application_BuildNumber on .Print_Date at .Print_Time" at 15.5,101 h1
  text ".ProjectRevisionART" at 335.678,-108.572 h1.5
  text ".Layer_Name" at 300.5,-108.75 h1.5
NOTES (M1):
  text ".Layer_Name" at 318.5,-108.75 h1.5
BOARD (M2):
  lines w0.1: 7.18,0 1,0 0,1 0,99 1,100 149,100 150,99 150,28 150,25.9 149,24.9 143.8,24.9 143.5,24.6 143.5,12.265 143.8,11.965 148.985,11.965 150,10.95 150,1 149,0 ; 21.48,0 149.02,0
  text ".ProjectRevisionART" at 335.678,-108.572 h1.5
  text ".Layer_Name" at 300.5,-108.75 h1.5
REF POINTS (M3):
  text ".Layer_Name" at 300.5,-108.75 h1.5
FAB (M4):
  drawing of 228 lines, arcs and shapes, not listed
  text "THIS PCB TO BE MANUFACTURED TO MEET ALL ACCEPTANCE LEVELS FROM CLASS 2:" at 233.389,104.437 h1.78
  text "IPC-6013" at 309.941,100.334 h1.78
  text "IPC-A-600" at 259.465,100.216 h1.78
  text "IPC-6012" at 287.405,100.216 h1.78
  text "STANDARD:" at 233.389,99.877 h1.78
  text "X" at 254.841,99.734 h2.6
  text "X" at 282.781,99.734 h2.6
  text "TG 170-180" at 309.891,95.584 h1.78
  text "TG 130-140" at 287.355,95.466 h1.78
  text "MATERIAL:" at 233.38,95.066 h1.78
  text "FR-4 or Equivalent" at 253.7,95.066 h1.78
  text "X" at 282.731,94.984 h2.6
  text "CONTROLLED IMPEDANCE" at 309.891,90.834 h1.78
  text "MULTILAYER" at 259.415,90.716 h1.78
  text "6" at 282.91,90.716 h1.78
  text "LAYERS" at 287.355,90.716 h1.78
  text "X" at 254.791,90.234 h2.6
  text "X" at 305.591,90.234 h2.6
  text "BURIED VIA" at 309.932,85.893 h1.78
  text "TH VIA" at 259.456,85.775 h1.78
  text "BLIND VIA" at 287.396,85.775 h1.78
  text "X" at 254.832,85.293 h2.6
  text "Cu WEIGHT EXTERNAL LAYERS" at 253.691,80.965 h1.78
  text "36um" at 305.761,80.965 h1.78
  text "FINISHED" at 315.286,80.965 h1.78
  text "18um" at 305.761,76.165 h1.78
  text "Cu WEIGHT INTERNAL LAYERS" at 253.691,76.115 h1.78
  text "FINISHED" at 315.286,76.115 h1.78
  text "FINISHED OVERALL THICKNESS" at 253.691,71.265 h1.78
  text "1.6" at 307.031,71.265 h1.78
  text "mm" at 315.286,71.265 h1.78
  text "10" at 329.891,71.265 h1.78
  text "%" at 338.146,71.265 h1.78
  text "PCB OUTLINE WIDTH" at 253.691,66.265 h1.78
  text "150" at 307.031,66.265 h1.78
  text "mm" at 315.286,66.265 h1.78
  text "0.1" at 329.891,66.265 h1.78
  text "mm" at 338.146,66.265 h1.78
  text "PCB OUTLINE HEIGHT" at 253.691,61.265 h1.78
  text "100" at 307.031,61.265 h1.78
  text "mm" at 315.286,61.265 h1.78
  text "0.1" at 329.891,61.265 h1.78
  text "mm" at 338.146,61.265 h1.78
  text "COPPER THIEVING ALLOWED" at 253.882,56.433 h1.78
  text "YES" at 310.882,56.433 h1.78
  text "NO" at 327.882,56.433 h1.78
  text "X" at 322.473,55.933 h2.6
  text "FINISH:" at 233.382,51.183 h1.78
  text "ENIG" at 259.382,50.883 h1.78
  text "X" at 254.682,50.263 h2.6
  text "IMMERSION SILVER" at 259.406,45.345 h1.78
  text "IMMERSION TIN" at 259.406,39.845 h1.78
  text "SMOBC WITH SELECTIVE GOLD PLATING ON LANDS" at 259.406,36.14 h1.78
  text "INDICATED. 1um GOLD OVER 5-10 um NICKEL" at 259.406,32.33 h1.78
  text "SOLDERMASK" at 253.691,25.495 h1.78
  text "IPC-SM-840 Class T" at 275.281,25.495 h1.78
  text "SOLDERMASK COLOR" at 253.691,19.145 h1.78
  text "GREEN HIGH GLOSS" at 285.441,19.145 h1.78
  text "SILKSCREEN COLOR" at 253.691,12.795 h1.78
  text "WHITE" at 285.441,12.795 h1.78
  text "ALL HOLES TO BE LOCATED BY THE COORDINATES FROM THE NC DRILL DATA PROVIDED." at 233.371,6.445 h1.78
  text "PCB REV" at 301.382,0.183 h1.78
  text "USE ARTWORK SET NO." at 233.371,0.095 h1.78
  text "'.ProjectPartNumber'" at 265.075,0.1 h1.78
  text ".ProjectRevisionART" at 314.532,-0.067 h1.78
  text "ALL UL LOGO, MANUFACTURER'S ID, AND DATE CODES SHALL BE PLACED" at 233.371,-6.255 h1.78
  text "ON THE BOTTOM SIDE UNLESS OTHERWISE INDICATED." at 233.371,-10.065 h1.78
  text "ANY ALTERNATIVES TO THE ABOVE SPECIFICATIONS MUST FIRST BE APPROVED." at 232.882,-15.317 h1.78
  text "Layer" at 234.225,-26.85 h1.5
  text "Name" at 242.731,-26.85 h1.5
  text "Material" at 261.649,-26.85 h1.5
  text "Thickness" at 278.011,-26.85 h1.5
  text "Constant" at 290.737,-26.85 h1.5
  text "Gerber" at 302.857,-26.85 h1.5
  text "Top Overlay" at 242.731,-29.85 h1.5
  text "GTO" at 302.857,-29.85 h1.5
  text "Top Solder" at 242.731,-32.85 h1.5
  text "Solder Resist" at 261.649,-32.85 h1.5
  text "0.025mm" at 278.011,-32.85 h1.5
  text "3.5" at 290.737,-32.85 h1.5
  text "GTS" at 302.857,-32.85 h1.5
  text "1" at 234.225,-35.85 h1.5
  text "L1 - TOP" at 242.731,-35.85 h1.5
  text "Copper" at 261.649,-35.85 h1.5
  text "0.036mm" at 278.011,-35.85 h1.5
  text "GTL" at 302.857,-35.85 h1.5
  text "Dielectric 1" at 242.731,-38.85 h1.5
  text "Prepreg" at 261.649,-38.85 h1.5
  text "0.085mm" at 278.011,-38.85 h1.5
  text "4.2" at 290.737,-38.85 h1.5
  text "THIS BOARD CONTAINS CONTROLLED IMPEDANCE TRACKS, TRACK AND GAP SIZES ARE AS FOLLOWS:" at 111.5,-41.225 h1.5
  text "2" at 234.225,-41.85 h1.5
  text "L2 - GND" at 242.731,-41.85 h1.5
  text "Copper" at 261.649,-41.85 h1.5
  text "0.018mm" at 278.011,-41.85 h1.5
  text "G1" at 302.857,-41.85 h1.5
  text "Dielectric 2" at 242.731,-44.85 h1.5
  text "FR-4" at 261.649,-44.85 h1.5
  text "0.100mm" at 278.011,-44.85 h1.5
  text "4.2" at 290.737,-44.85 h1.5
  text "TYPE;" at 111.5,-46.225 h1.5
  text "Impedance;" at 123,-46.225 h1.5
  text "Tolerance;" at 140.5,-46.225 h1.5
  text "Layer;" at 157.5,-46.225 h1.5
  text "Reference;" at 169.5,-46.225 h1.5
  text "Width (um);" at 186.5,-46.225 h1.5
  text "Gap (um);" at 206.5,-46.225 h1.5
  text "3" at 234.225,-47.85 h1.5
  text "L3 - SIG" at 242.731,-47.85 h1.5
  text "Copper" at 261.649,-47.85 h1.5
  text "0.018mm" at 278.011,-47.85 h1.5
  text "G2" at 302.857,-47.85 h1.5
  text "DIFF;" at 111.5,-50.725 h1.5
  text "90ohm;" at 123,-50.725 h1.5
  text "+/- 15%;" at 140.5,-50.725 h1.5
  text "L1;" at 157.5,-50.725 h1.5
  text "L2;" at 169.5,-50.725 h1.5
  text "135;" at 186.5,-50.725 h1.5
  text "200;" at 206.5,-50.725 h1.5
  text "Dielectric 3" at 242.731,-50.85 h1.5
  text "Prepreg" at 261.649,-50.85 h1.5
  text "1.000mm" at 278.011,-50.85 h1.5
  text "4.1" at 290.737,-50.85 h1.5
  text "DIFF;" at 111.5,-53.225 h1.5
  text "90ohm;" at 123,-53.225 h1.5
  text "+/- 15%;" at 140.5,-53.225 h1.5
  text "L6;" at 157.5,-53.225 h1.5
  text "L5;" at 169.5,-53.225 h1.5
  text "135;" at 186.5,-53.225 h1.5
  text "200;" at 206.5,-53.225 h1.5
  text "4" at 234.225,-53.85 h1.5
  text "L4 - SIG" at 242.731,-53.85 h1.5
  text "Copper" at 261.649,-53.85 h1.5
  text "0.018mm" at 278.011,-53.85 h1.5
  text "G3" at 302.857,-53.85 h1.5
  text "DIFF;" at 111.5,-56.725 h1.5
  text "100ohm;" at 123,-56.725 h1.5
  text "+/- 10%;" at 140.5,-56.725 h1.5
  text "L1;" at 157.5,-56.725 h1.5
  text "L2;" at 169.5,-56.725 h1.5
  text "100;" at 186.5,-56.725 h1.5
  text "200;" at 206.5,-56.725 h1.5
  text "Dielectric 4" at 242.731,-56.85 h1.5
  text "FR-4" at 261.649,-56.85 h1.5
  text "0.100mm" at 278.011,-56.85 h1.5
  text "4.2" at 290.737,-56.85 h1.5
  text "DIFF;" at 111.5,-59.225 h1.5
  text "100ohm;" at 123,-59.225 h1.5
  text "+/- 10%;" at 140.5,-59.225 h1.5
  text "L6;" at 157.5,-59.225 h1.5
  text "L5;" at 169.5,-59.225 h1.5
  text "100;" at 186.5,-59.225 h1.5
  text "200;" at 206.5,-59.225 h1.5
  text "5" at 234.225,-59.85 h1.5
  text "L5 - VCC" at 242.731,-59.85 h1.5
  text "Copper" at 261.649,-59.85 h1.5
  text "0.018mm" at 278.011,-59.85 h1.5
  text "G4" at 302.857,-59.85 h1.5
  text "DIFF;" at 111.5,-62.725 h1.5
  text "100ohm;" at 123,-62.725 h1.5
  text "+/- 10%;" at 140.5,-62.725 h1.5
  text "L3;" at 157.5,-62.725 h1.5
  text "L2;" at 169.5,-62.725 h1.5
  text "100;" at 186.5,-62.725 h1.5
  text "225;" at 206.5,-62.725 h1.5
  text "Dielectric 5" at 242.731,-62.85 h1.5
  text "Prepreg" at 261.649,-62.85 h1.5
  text "0.085mm" at 278.011,-62.85 h1.5
  text "4.2" at 290.737,-62.85 h1.5
  text "DIFF;" at 111.5,-65.225 h1.5
  text "100ohm;" at 123,-65.225 h1.5
  text "+/- 10%;" at 140.5,-65.225 h1.5
  text "L4;" at 157.5,-65.225 h1.5
  text "L5;" at 169.5,-65.225 h1.5
  text "100;" at 186.5,-65.225 h1.5
  text "225;" at 206.5,-65.225 h1.5
  text "6" at 234.225,-65.85 h1.5
  text "L6 - BOT" at 242.731,-65.85 h1.5
  text "Copper" at 261.649,-65.85 h1.5
  text "0.036mm" at 278.011,-65.85 h1.5
  text "GBL" at 302.857,-65.85 h1.5
  text "SE;" at 111.5,-68.725 h1.5
  text "50ohm;" at 123,-68.725 h1.5
  text "+/- 10%;" at 140.5,-68.725 h1.5
  text "L1;" at 157.5,-68.725 h1.5
  text "L2;" at 169.5,-68.725 h1.5
  text "125;" at 186.5,-68.725 h1.5
  text "Bottom Solder" at 242.731,-68.85 h1.5
  text "Solder Resist" at 261.649,-68.85 h1.5
  text "0.025mm" at 278.011,-68.85 h1.5
  text "3.5" at 290.737,-68.85 h1.5
  text "GBS" at 302.857,-68.85 h1.5
  text "SE;" at 111.5,-71.225 h1.5
  text "50ohm;" at 123,-71.225 h1.5
  text "+/- 10%;" at 140.5,-71.225 h1.5
  text "L6;" at 157.5,-71.225 h1.5
  text "L5;" at 169.5,-71.225 h1.5
  text "125;" at 186.5,-71.225 h1.5
  text "Bottom Overlay" at 242.731,-71.85 h1.5
  text "GBO" at 302.857,-71.85 h1.5
  text "SE;" at 111.5,-74.725 h1.5
  text "50ohm;" at 123,-74.725 h1.5
  text "+/- 10%;" at 140.5,-74.725 h1.5
  text "L3;" at 157.5,-74.725 h1.5
  text "L2;" at 169.5,-74.725 h1.5
  text "125;" at 186.5,-74.725 h1.5
  text "Total board thickness:" at 234.225,-74.85 h1.5
  text "1.562mm" at 278.011,-74.85 h1.5
  text "SE;" at 111.5,-77.225 h1.5
  text "50ohm;" at 123,-77.225 h1.5
  text "+/- 10%;" at 140.5,-77.225 h1.5
  text "L4;" at 157.5,-77.225 h1.5
  text "L5;" at 169.5,-77.225 h1.5
  text "125;" at 186.5,-77.225 h1.5
  text ".ProjectRevisionFAB" at 335.678,-108.572 h1.5
  text ".Layer_Name" at 300.5,-108.75 h1.5
Case (M5):
  text ".Layer_Name" at 300.5,-108.75 h1.5
Cover (M6):
  text ".Layer_Name" at 300.5,-108.75 h1.5
Terminal Block (M7):
  text ".Layer_Name" at 300.5,-108.75 h1.5
Route Tool Path:
  text ".Layer_Name" at 300.5,-108.75 h1.5
V-Cut (M9):
  text ".Layer_Name" at 300.5,-108.75 h1.5
Assy BOT (M10):
  text ".variantName" at 50.07,-92.75 h0.22
  text "ASSEMBLY VARIANT:" at 64.32,-92.75 h0.22
  text "DOCUMENT NUMBER:" at 18.05,-101 h0.22
  text ".ProjectRevisionASSY" at 1.122,-108.572 h0.22
  text ".Layer_Name" at 36,-108.75 h0.22
Assy TOP (M11):
  text "U4" at 61,48.4 h2
  text "ASSEMBLY NOTES:" at 142.8,-11.6 h4
  text "1. ALL COMPONENTS SHALL BE RoHS COMPLIANT." at 108.7,-16.7 h3
  text "2. ALL UNUSED THROUGH HOLE COMPONENT LOCATIONS SHALL BE FREE OF SOLDER." at 108.7,-19.7 h3
  text "3. ALL COMPONENTS SHALL BE MOUNTED FLUSH TO THE BOARD, EXCEPT AS NOTED." at 108.7,-22.7 h3
  text "4. FINISHED BOARD SHALL BE FREE OF ALL RESIDUES." at 108.7,-25.7 h3
  text "5. ALL LEADS SHALL BE TRIMMED TO A MAXIMUM HEIGHT OF 2mm" at 108.7,-28.7 h3
  text "6. PLACE LABEL  ON THE LOCATION INDICATED." at 108.7,-31.7 h3
  text "ASSEMBLY VARIANT:" at 272.5,-92.75 h0.9
  text ".variantName" at 286.75,-92.75 h0.9
  text "DOCUMENT NUMBER:" at 318.75,-101 h1.14
  text ".ProjectRevisionASSY" at 335.678,-108.572 h1.5
  text ".Layer_Name" at 300.5,-108.75 h1.5
3D BOT (M12):
  text ".Layer_Name" at 300.5,-108.75 h1.5
3D TOP (M13):
  text ".Layer_Name" at 300.5,-108.75 h1.5
Guard BOT (M14):
  text ".ProjectRevisionART" at 335.678,-108.572 h1.5
  text ".Layer_Name" at 300.5,-108.75 h1.5
Guard TOP (M15):
  text ".ProjectRevisionART" at 335.678,-108.572 h1.5
  text ".Layer_Name" at 300.5,-108.75 h1.5
TITLE (M16):
  lines w0.1: 272,-91.5 353.82,-91.5 ; 324.9,-84 324.9,-87 353.82,-87 ; 342.54,-108.635 342.54,-107.365 ; 342.54,-108 352.7,-108 ; 342.7,-106.8 342.7,-105.8 ; 342.7,-106.3 352.7,-106.3 ; 345.08,-108.635 345.08,-107.365 ; 347.62,-108.635 347.62,-107.365 ; 347.7,-106.6 347.7,-106 ; 350.16,-108.635 350.16,-107.365 ; 352.7,-108.635 352.7,-107.365 ; 352.7,-106.8 352.7,-105.8 ; 353.82,-87 353.82,-87
  lines w0.127: -22.1,-54.175 -17.02,-54.175 ; -22.1,6.15 -17.02,6.15 ; -22.1,66.475 -17.02,66.475 ; 41.4,-114.5 41.4,-109.42 ; 41.4,121.72 41.4,126.8 ; 104.9,-114.5 104.9,-109.42 ; 104.9,121.72 104.9,126.8 ; 168.4,-114.5 168.4,-109.42 ; 168.4,121.72 168.4,126.8 ; 203.96,-109.42 239.52,-109.42 ; 231.9,-114.5 231.9,-109.42 ; 231.9,121.72 231.9,126.8 ; 238,-109.42 238,-84 353.82,-84 ; 272,-109.42 272,-84 ; 272,-105 353.82,-105 ; 272,-99 353.82,-99 ; 272,-93 353.82,-93 ; 295.4,-114.5 295.4,-109.42 ; 295.4,121.72 295.4,126.8 ; 300,-109.42 300,-93 ; 318,-105 318,-99 ; 331,-109.42 331,-105 ; 338.5,-109.42 338.5,-99 ; 353.82,-78.94 353.82,-109.42 ; 353.82,-54.175 358.9,-54.175 ; 353.82,6.15 358.9,6.15 ; 353.82,66.475 358.9,66.475 ; 353.82,-109.42 -17.02,-109.42 -17.02,121.72 353.82,121.72 353.82,-109.42 ; -22.1,-114.5 358.9,-114.5 358.9,126.8 -22.1,126.8 -22.1,-114.5
  lines w0.254: 232,121.5 232,117 ; 243,112.5 243,117 243,121.5 ; 255.5,112.5 255.5,117 255.5,121.5 ; 334,112.5 334,117 334,121.5 ; 353.5,112.5 232,112.5 232,117 ; 353.5,117 232,117
  text "1" at 9.176,123.498 h1.78
  text "2" at 72.566,123.498 h1.78
  text "3" at 135.795,123.498 h1.78
  text "4" at 199.464,123.498 h1.78
  text "5" at 262.939,123.498 h1.78
  text "6" at 326.566,123.498 h1.78
  text "REV" at 234.5,118.5 h1.52
  text "ECO" at 244.5,118.5 h1.52
  text "Comments" at 291,118 h1.52
  text "Date" at 339,118 h1.52
  text "A" at -20.195,94.466 h1.78
  text "A" at 355.725,94.466 h1.78
  text "B" at -20.195,34.014 h1.78
  text "B" at 355.725,34.014 h1.78
  text "C" at -20.195,-26.311 h1.78
  text "C" at 355.725,-26.311 h1.78
  text "PART NUMBER:" at 326.3,-86 h1
  text ".ProjectpartNumber" at 338.3,-86.25 h1.5
  text "D" at -20.195,-86.509 h1.78
  text "TITLE:" at 273,-86.5 h1.14
  text "D" at 355.725,-86.509 h1.78
  text ".ProjectTitle" at 273,-90.5 h2.5
  text "PCB DESIGNER:" at 273,-95 h1.14
  text "GERBER FILE:" at 301,-95 h1.14
  text ".ProjectDrawnBy" at 273,-98 h1.78
  text ".Plot_File_Name" at 301,-98 h1.5
  text "M" at 241,-100 h15.24
  text "ENGINEER:" at 273,-101 h1.14
  text "BOARD NUMBER:" at 301,-101 h1.14
  text "DATE:" at 339.7,-101 h1.14
  text "Microchip Technology Inc." at 239.77,-103.26 h1.78
  text "'.ProjectPartNumber'" at 301.4,-103.7 h1.2
  text ".ProjectEngineer" at 273,-104 h1.78
  text ".PRINT_DATE" at 339.7,-104 h1.5
  text "2355 W. Chandler Blvd." at 241,-106 h1.78
  text "LAYER NAME:" at 301,-106.5 h1.14
  text "10mm" at 339,-106.6 h0.7
  text "PCB FILE NAME:" at 273,-106.75 h1.14
  text "REV:" at 331.75,-106.75 h1.14
  text "400mil" at 338.9,-108.3 h0.7
  text "Chandler, AZ  85224" at 242,-108.5 h1.78
  text ".PCB_FILE_NAME_NO_PATH" at 273,-108.75 h1.14
  text "1" at 9.176,-112.722 h1.78
  text "2" at 72.566,-112.722 h1.78
  text "3" at 135.795,-112.722 h1.78
  text "4" at 199.464,-112.722 h1.78
  text "5" at 262.939,-112.722 h1.78
  text "6" at 326.566,-112.722 h1.78
Drill Drawing:
  drawing of 158 lines, arcs and shapes, not listed
  text "Symbol" at -13.063,-9.7 h1.8
  text "Hit Count" at -1.943,-9.7 h1.8
  text "Finished Hole Size" at 12.313,-9.7 h1.8
  text "Plated" at 37.187,-9.7 h1.8
  text "Hole Type" at 46.79,-9.7 h1.8
  text "Hole Length" at 61.2,-9.7 h1.8
  text "Routed Path Length" at 77.787,-9.7 h1.8
  text "1" at -1.943,-13.45 h1.5
  text "1.00mm" at 12.313,-13.45 h1.5
  text "PTH" at 37.187,-13.45 h1.5
  text "Slot" at 46.79,-13.45 h1.5
  text "3.50mm" at 61.2,-13.45 h1.5
  text "2.50mm" at 77.787,-13.45 h1.5
  text "D" at -13.721,-13.6 h1.67
  text "2" at -1.943,-17.2 h1.5
  text "1.00mm" at 12.313,-17.2 h1.5
  text "PTH" at 37.187,-17.2 h1.5
  text "Slot" at 46.79,-17.2 h1.5
  text "3.00mm" at 61.2,-17.2 h1.5
  text "2.00mm" at 77.787,-17.2 h1.5
  text "C" at -13.721,-17.35 h1.67
  text "2" at -1.943,-20.95 h1.5
  text "1.50mm" at 12.313,-20.95 h1.5
  text "NPTH" at 37.187,-20.95 h1.5
  text "Round" at 46.79,-20.95 h1.5
  text "-" at 61.2,-20.95 h1.5
  text "-" at 77.787,-20.95 h1.5
  text "B" at -13.721,-21.1 h1.67
  text "2" at -1.943,-24.7 h1.5
  text "3.25mm" at 12.313,-24.7 h1.5
  text "NPTH" at 37.187,-24.7 h1.5
  text "Round" at 46.79,-24.7 h1.5
  text "-" at 61.2,-24.7 h1.5
  text "-" at 77.787,-24.7 h1.5
  text "4" at -1.943,-28.45 h1.5
  text "0.60mm" at 12.313,-28.45 h1.5
  text "PTH" at 37.187,-28.45 h1.5
  text "Slot" at 46.79,-28.45 h1.5
  text "1.30mm" at 61.2,-28.45 h1.5
  text "0.70mm" at 77.787,-28.45 h1.5
  text "4" at -1.943,-32.2 h1.5
  text "0.65mm" at 12.313,-32.2 h1.5
  text "PTH" at 37.187,-32.2 h1.5
  text "Slot" at 46.79,-32.2 h1.5
  text "0.85mm" at 61.2,-32.2 h1.5
  text "0.20mm" at 77.787,-32.2 h1.5
  text "4" at -1.943,-35.95 h1.5
  text "1.20mm" at 12.313,-35.95 h1.5
  text "PTH" at 37.187,-35.95 h1.5
  text "Round" at 46.79,-35.95 h1.5
  text "-" at 61.2,-35.95 h1.5
  text "-" at 77.787,-35.95 h1.5
  text "4" at -1.943,-39.7 h1.5
  text "3.20mm" at 12.313,-39.7 h1.5
  text "NPTH" at 37.187,-39.7 h1.5
  text "Round" at 46.79,-39.7 h1.5
  text "-" at 61.2,-39.7 h1.5
  text "-" at 77.787,-39.7 h1.5
  text "5" at -1.943,-43.45 h1.5
  text "1.10mm" at 12.313,-43.45 h1.5
  text "PTH" at 37.187,-43.45 h1.5
  text "Round" at 46.79,-43.45 h1.5
  text "-" at 61.2,-43.45 h1.5
  text "-" at 77.787,-43.45 h1.5
  text "6" at -1.943,-47.2 h1.5
  text "0.60mm" at 12.313,-47.2 h1.5
  text "PTH" at 37.187,-47.2 h1.5
  text "Round" at 46.79,-47.2 h1.5
  text "-" at 61.2,-47.2 h1.5
  text "-" at 77.787,-47.2 h1.5
  text "8" at -1.943,-50.95 h1.5
  text "2.30mm" at 12.313,-50.95 h1.5
  text "PTH" at 37.187,-50.95 h1.5
  text "Round" at 46.79,-50.95 h1.5
  text "-" at 61.2,-50.95 h1.5
  text "-" at 77.787,-50.95 h1.5
  text "8" at -1.943,-54.7 h1.5
  text "3.20mm" at 12.313,-54.7 h1.5
  text "NPTH" at 37.187,-54.7 h1.5
  text "Round" at 46.79,-54.7 h1.5
  text "-" at 61.2,-54.7 h1.5
  text "-" at 77.787,-54.7 h1.5
  text "10" at -1.943,-58.45 h1.5
  text "1.60mm" at 12.313,-58.45 h1.5
  text "PTH" at 37.187,-58.45 h1.5
  text "Round" at 46.79,-58.45 h1.5
  text "-" at 61.2,-58.45 h1.5
  text "-" at 77.787,-58.45 h1.5
  text "32" at -1.943,-62.2 h1.5
  text "1.00mm" at 12.313,-62.2 h1.5
  text "PTH" at 37.187,-62.2 h1.5
  text "Round" at 46.79,-62.2 h1.5
  text "-" at 61.2,-62.2 h1.5
  text "-" at 77.787,-62.2 h1.5
  text "100" at -1.943,-65.95 h1.5
  text "0.30mm" at 12.313,-65.95 h1.5
  text "PTH" at 37.187,-65.95 h1.5
  text "Round" at 46.79,-65.95 h1.5
  text "-" at 61.2,-65.95 h1.5
  text "-" at 77.787,-65.95 h1.5
  text "F" at -13.721,-66.1 h1.67
  text "111" at -1.943,-69.7 h1.5
  text "0.90mm" at 12.313,-69.7 h1.5
  text "PTH" at 37.187,-69.7 h1.5
  text "Round" at 46.79,-69.7 h1.5
  text "-" at 61.2,-69.7 h1.5
  text "-" at 77.787,-69.7 h1.5
  text "1337" at -1.943,-73.45 h1.5
  text "0.20mm" at 12.313,-73.45 h1.5
  text "PTH" at 37.187,-73.45 h1.5
  text "Round" at 46.79,-73.45 h1.5
  text "-" at 61.2,-73.45 h1.5
  text "-" at 77.787,-73.45 h1.5
  text "E" at -13.721,-73.6 h1.67
  text "1640 Total" at -1.943,-77.2 h1.5
  text "Slot definitions :" at -13.063,-80.625 h1.5
  text "Routed Path Length" at 5.043,-80.625 h1.5
  text "= Calculated from tool start centre position to tool end centre position." at 26.698,-80.625 h1.5
  text "Hole Length" at 5.043,-82.924 h1.5
  text "= Routed Path Length + Tool Size = Slot length as defined in the PCB layout" at 18.136,-82.924 h1.5
  text "DOCUMENT NUMBER:" at 318.75,-101 h1.14
  text ".ProjectRevisionFAB" at 335.678,-108.572 h1.5
TITLE MIRROR (M17):
  lines w0.1: -17,-91.5 64.82,-91.5 ; -15.9,-108.635 -15.9,-107.365 ; -15.9,-108 -5.74,-108 ; -15.9,-106.8 -15.9,-105.8 ; -15.9,-106.3 -5.9,-106.3 ; -13.36,-108.635 -13.36,-107.365 ; -10.9,-106.6 -10.9,-106 ; -10.82,-108.635 -10.82,-107.365 ; -8.28,-108.635 -8.28,-107.365 ; -5.9,-106.8 -5.9,-105.8 ; -5.74,-108.635 -5.74,-107.365 ; 12.9,-84 12.9,-87 -17,-87 ; -17,-87 -17,-87
  lines w0.127: -22.1,-54.175 -17.02,-54.175 ; -22.1,6.15 -17.02,6.15 ; -22.1,66.475 -17.02,66.475 ; -17.02,-105 64.8,-105 ; -17.02,-99 64.8,-99 ; -17,-93 64.82,-93 ; -17,-84 98.82,-84 98.82,-109.42 ; -1.7,-109.42 -1.7,-99 ; 5.8,-109.42 5.8,-105 ; 18.8,-105 18.8,-99 ; 36.82,-109.42 36.82,-93 ; 41.4,-114.5 41.4,-109.42 ; 41.4,121.72 41.4,126.8 ; 64.82,-109.42 64.82,-84 ; 104.9,-114.5 104.9,-109.42 ; 104.9,121.72 104.9,126.8 ; 168.4,-114.5 168.4,-109.42 ; 168.4,121.72 168.4,126.8 ; 231.9,-114.5 231.9,-109.42 ; 231.9,121.72 231.9,126.8 ; 295.4,-114.5 295.4,-109.42 ; 295.4,121.72 295.4,126.8 ; 353.82,-54.175 358.9,-54.175 ; 353.82,6.15 358.9,6.15 ; 353.82,66.475 358.9,66.475 ; -22.1,-114.5 -22.1,126.8 358.9,126.8 358.9,-114.5 -22.1,-114.5 ; -17.02,-109.42 -17.02,121.72 353.82,121.72 353.82,-109.42 -17.02,-109.42
  text "6" at 10.234,123.498 h1.78
  text "5" at 73.861,123.498 h1.78
  text "4" at 137.336,123.498 h1.78
  text "3" at 201.005,123.498 h1.78
  text "2" at 264.234,123.498 h1.78
  text "1" at 327.624,123.498 h1.78
  text "A" at -18.925,94.466 h1.78
  text "A" at 356.995,94.466 h1.78
  text "B" at -18.925,34.014 h1.78
  text "B" at 356.995,34.014 h1.78
  text "C" at -18.925,-26.311 h1.78
  text "C" at 356.995,-26.311 h1.78
  text "PART NUMBER:" at 11.02,-86 h1
  text "TITLE:" at 63.82,-86 h1.14
  text ".ProjectpartNumber" at -0.98,-86.25 h1.5
  text "D" at -18.925,-86.509 h1.78
  text "D" at 356.995,-86.509 h1.78
  text ".ProjectTitle" at 63.82,-90.5 h2.5
  text "GERBER FILE:" at 35.82,-95 h1.14
  text "PCB DESIGNER:" at 63.82,-95 h1.14
  text ".Plot_File_Name" at 35.82,-98 h1.5
  text ".ProjectDrawnBy" at 63.82,-98 h1.78
  text "M" at 95.82,-100 h15.24
  text "DATE:" at -2.9,-101 h1.14
  text "BOARD NUMBER:" at 35.8,-101 h1.14
  text "ENGINEER:" at 63.8,-101 h1.14
  text "Microchip Technology Inc." at 97.05,-103.26 h1.78
  text "'.ProjectPartNumber'" at 34.9,-103.6 h1.2
  text ".PRINT_DATE" at -2.9,-104 h1.5
  text ".ProjectEngineer" at 63.8,-104 h1.78
  text "2355 W. Chandler Blvd." at 95.82,-106 h1.78
  text "LAYER NAME:" at 35.8,-106.5 h1.14
  text "10mm" at -2.2,-106.6 h0.7
  text "REV:" at 5.05,-106.75 h1.14
  text "PCB FILE NAME:" at 63.8,-106.75 h1.14
  text "400mil" at -2.1,-108.3 h0.7
  text "Chandler, AZ  85224" at 94.82,-108.5 h1.78
  text ".PCB_FILE_NAME_NO_PATH" at 63.8,-108.75 h1.14
  text "6" at 10.234,-112.722 h1.78
  text "5" at 73.861,-112.722 h1.78
  text "4" at 137.336,-112.722 h1.78
  text "3" at 201.005,-112.722 h1.78
  text "2" at 264.234,-112.722 h1.78
  text "1" at 327.624,-112.722 h1.78

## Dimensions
150.4,0 to 150.1,100 on FAB (M4)
150,-0.7 to 0,0 on FAB (M4)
